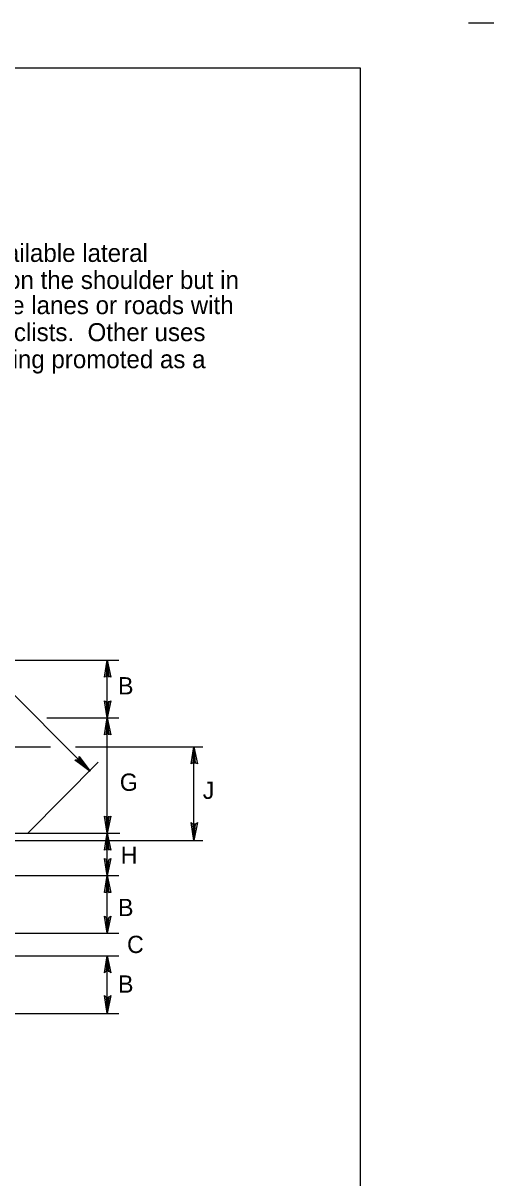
# Model space of a CAD drawing. Extents: x -0.018 to 0.195, y -0.006 to 0.263.
# Drawn here: x 0.1297 to 0.195, y 0.1026 to 0.2627 of the extents above; entities that cross this region are included whole.
import ezdxf

# ---------------------------------------------------------------- set-up
doc = ezdxf.new("R2010")
doc.units = 0
doc.layers.add('1', color=7, linetype='Continuous')
doc.layers.add('3', color=7, linetype='Continuous')

msp = doc.modelspace()

# ---------------------------------------------------------------- linework, layer by layer
at = {"layer": '1'}
for p, q in [((0.195, 0.26275), (0.1915, 0.26275)), ((0.1765, 0.2565), (0, 0.2565)), ((0.1765, 0), (0.1765, 0.2565)), ((0.119, 0.179), (0.139, 0.159)), ((0.12525, 0.17438), (0.143, 0.17438)), ((0.14138, 0.16637), (0.14138, 0.17438)), ((0.133, 0.16637), (0.143, 0.16637)), ((0.14138, 0.15038), (0.14138, 0.16637)), ((0.1135, 0.16237), (0.1335, 0.16237)), ((0.137, 0.16237), (0.15463, 0.16237)), ((0.15338, 0.14938), (0.15338, 0.16237)), ((0.13037, 0.15038), (0.14012, 0.16025)), ((0.03238, 0.15038), (0.14313, 0.15038)), ((0.11213, 0.14938), (0.15463, 0.14938)), ((0.14138, 0.1445), (0.14138, 0.15038)), ((0.09788, 0.1445), (0.143, 0.1445)), ((0.14138, 0.1365), (0.14138, 0.1445)), ((0.09788, 0.1365), (0.143, 0.1365)), ((0.10138, 0.13337), (0.143, 0.13337)), ((0.14138, 0.12538), (0.14138, 0.13337)), ((0.10138, 0.12538), (0.143, 0.12538))]:
    msp.add_line(p, q, dxfattribs=at)
for points in [[(0.14125, 0.17213), (0.14138, 0.17213), (0.14138, 0.17438), (0.14125, 0.17213), (0.141, 0.172), (0.14138, 0.17438), (0.1415, 0.17213), (0.14163, 0.17213), (0.14138, 0.17438), (0.14188, 0.172), (0.14163, 0.17213)], [(0.14163, 0.16862), (0.1415, 0.16862), (0.14138, 0.16637), (0.14163, 0.16862), (0.14188, 0.16875), (0.14138, 0.16637), (0.14138, 0.16862), (0.14125, 0.16862), (0.14138, 0.16637), (0.141, 0.16875), (0.14125, 0.16862)], [(0.14125, 0.16412), (0.14138, 0.16412), (0.14138, 0.16637), (0.14125, 0.16412), (0.141, 0.164), (0.14138, 0.16637), (0.1415, 0.16412), (0.14163, 0.16412), (0.14138, 0.16637), (0.14188, 0.164), (0.14163, 0.16412)], [(0.15325, 0.16012), (0.15338, 0.16012), (0.15338, 0.16237), (0.15325, 0.16012), (0.153, 0.16), (0.15338, 0.16237), (0.1535, 0.16012), (0.15363, 0.16012), (0.15338, 0.16237), (0.15388, 0.16), (0.15363, 0.16012)], [(0.1375, 0.16075), (0.1375, 0.16062), (0.139, 0.159), (0.1375, 0.16075), (0.1375, 0.161), (0.139, 0.159), (0.13725, 0.1605), (0.137, 0.1605), (0.139, 0.159), (0.13687, 0.1605), (0.137, 0.1605)], [(0.14163, 0.15263), (0.1415, 0.15263), (0.14138, 0.15038), (0.14163, 0.15263), (0.14188, 0.15275), (0.14138, 0.15038), (0.14138, 0.15263), (0.14125, 0.15263), (0.14138, 0.15038), (0.141, 0.15275), (0.14125, 0.15263)], [(0.15363, 0.15163), (0.1535, 0.15163), (0.15338, 0.14938), (0.15363, 0.15163), (0.15388, 0.15188), (0.15338, 0.14938), (0.15338, 0.15163), (0.15325, 0.15163), (0.15338, 0.14938), (0.153, 0.15188), (0.15325, 0.15163)], [(0.14125, 0.14813), (0.14138, 0.14813), (0.14138, 0.15038), (0.14125, 0.14813), (0.141, 0.148), (0.14138, 0.15038), (0.1415, 0.14813), (0.14163, 0.14813), (0.14138, 0.15038), (0.14188, 0.148), (0.14163, 0.14813)], [(0.14163, 0.14675), (0.1415, 0.1465), (0.14138, 0.1445), (0.14163, 0.14675), (0.14188, 0.14688), (0.14138, 0.1445), (0.14138, 0.1465), (0.14125, 0.14675), (0.14138, 0.1445), (0.141, 0.14688), (0.14125, 0.14675)], [(0.14125, 0.14213), (0.14138, 0.14225), (0.14138, 0.1445), (0.14125, 0.14213), (0.141, 0.14213), (0.14138, 0.1445), (0.1415, 0.14225), (0.14163, 0.14213), (0.14138, 0.1445), (0.14188, 0.14213), (0.14163, 0.14213)], [(0.14163, 0.13875), (0.1415, 0.1385), (0.14138, 0.1365), (0.14163, 0.13875), (0.14188, 0.13887), (0.14138, 0.1365), (0.14138, 0.1385), (0.14125, 0.13875), (0.14138, 0.1365), (0.141, 0.13887), (0.14125, 0.13875)], [(0.14125, 0.13125), (0.14138, 0.13125), (0.14138, 0.13337), (0.14125, 0.13125), (0.141, 0.131), (0.14138, 0.13337), (0.1415, 0.13125), (0.14163, 0.13125), (0.14138, 0.13337), (0.14188, 0.131), (0.14163, 0.13125)], [(0.14163, 0.12763), (0.1415, 0.12763), (0.14138, 0.12538), (0.14163, 0.12763), (0.14188, 0.12788), (0.14138, 0.12538), (0.14138, 0.12763), (0.14125, 0.12763), (0.14138, 0.12538), (0.141, 0.12788), (0.14125, 0.12763)]]:
    msp.add_lwpolyline(points, dxfattribs=at)

# ---------------------------------------------------------------- texts
for s, p in [('B', (0.14288, 0.16962)), ('G', (0.14313, 0.15625)), ('J', (0.15463, 0.15513)), ('H', (0.14325, 0.14613)), ('B', (0.14288, 0.13887)), ('C', (0.14413, 0.13375)), ('B', (0.14288, 0.12825))]:
    msp.add_text(s, height=0.0024, dxfattribs=at).set_placement(p)
at = {"layer": '3'}
for s, height, p in [('     The Share the Road Sign (W15-3) may be used on highways where available lateral', 0.0024998, (0.01788, 0.22962)), ('clearances make it likely that bicyclists will either travel on the roadway or on the shoulder but in', 0.00249975, (0.01788, 0.22587)), ('close proximity to the roadway.  It may also be used in conjunction with bike lanes or roads with', 0.0024998, (0.01788, 0.22238)), ('wide paved shoulders if the intent is to alert motorists to the presence of cyclists.  Other uses', 0.0024998, (0.01788, 0.21863)), ('may include roads with a documented car-bike crash history and a road being promoted as a', 0.0024998, (0.01788, 0.21488))]:
    msp.add_text(s, height=height, dxfattribs=at).set_placement(p)

doc.saveas('drawing.dxf')
